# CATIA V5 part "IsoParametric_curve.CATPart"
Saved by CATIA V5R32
Part number: Part1
Bounding box of the stored display mesh (mm): x -201.73 to 99, y -122.834 to 226.104, z -13.805 to 30.749
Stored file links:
  D:\PROJECTS\Project 2022\CATIA V5 6R 2022\Resources\Part Files\c17_catia_v6_6r2022_prt\IsoParametric_curve.CATPart
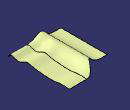
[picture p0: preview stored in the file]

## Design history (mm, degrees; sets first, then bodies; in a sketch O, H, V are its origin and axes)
Body1 (main body)
  Sketch1 on yz-plane, origin (0, 0, 0), H (0, 1, 0), V (0, 0, 1)
    spline S1 through (-122.8344, -6.7669) (-106.6526, 10.0033) (-67.8164, 0) (-14.2694, 18.5355) (14.5636, 14.4165) (64.8742, 7.0611) (133.1319, 3.8248) (184.3252, 10.0033) (226.1036, 7.0611)
    point P1 (-67.8164, 0)
    coincidence: P1 H
  Extrude1: Element1 Sketch1, Lim1 99, Lim2 0
  Sketch2 on zx-plane, origin (0, 0, 0), H (-1, 0, 0), V (0, 0, 1)
    spline S1 through (107.3762, 13.3919) (140.5417, -9.862) (187.902, -13.8052) (201.7301, -13.8052)
  Extrude2: Element1 Sketch2, Lim1 122, Lim2 142
  Blend1: StartLimit {blendlimit Curve edge of Extrude2, Support Extrude2}, EndLimit {blendlimit Curve Sketch1, Support Extrude1}
  Join1: Elements (Extrude2; Blend1; Extrude1)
